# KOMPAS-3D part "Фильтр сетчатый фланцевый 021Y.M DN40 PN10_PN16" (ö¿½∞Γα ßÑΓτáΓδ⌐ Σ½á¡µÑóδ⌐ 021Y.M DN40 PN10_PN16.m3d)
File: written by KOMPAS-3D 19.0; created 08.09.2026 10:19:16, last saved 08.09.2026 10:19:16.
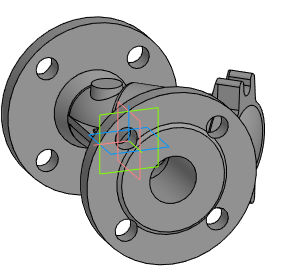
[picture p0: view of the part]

Document properties: Автор: Энергия; Полное имя файла: Z:\3.Личные\sachek\Dendor\_3D для проектировщиков\8.2 Фильтр сетчатый 021Y.M\021Y.M_STP\Фильтр сетчатый фланцевый 021Y.M DN40 PN10_PN16.m3d

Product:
- Part/product: Фильтр сетчатый фланцевый 021Y.M DN40 PN10_PN16

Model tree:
1. Операция без истории:1  (labels: Фильтр сетчатый фланцевый 021Y.M DN40 PN10_PN16)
